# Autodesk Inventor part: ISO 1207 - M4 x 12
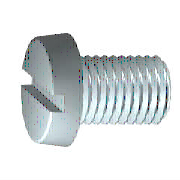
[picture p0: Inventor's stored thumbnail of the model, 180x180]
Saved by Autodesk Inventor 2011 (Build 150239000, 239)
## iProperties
IsCustomPart: 0
Created: 2010-02
Part Number: ISO 1207 - M4 x 12
Material: EdelStahl - 440C
Description: Zylinderkopfschrauben mit Schlitz - Produktklasse A
Document SubType Name: Modeling
Standard: ISO 1207
Designer: M.Schulte
Standard Revision: Third edition 1992-05-15
Standards Organization: ISO
Language: de-DE
Size Designation: M4 x 12
Categories: <MemberInstance><Categories><Category DisplayName="Verbindungselemente" InternalName="e4da775c-781d-43d5-af7c-5136215cf5a6" Mnemonic="FSTN"><Category DisplayNam
Density: 7.75 g/cm^3
Author: M.Schulte
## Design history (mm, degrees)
body "Solid1"
sketch "Sketch1"
  geometry: L1 (-2.6, 0)-(12, 0); L2 (12, 0)-(12, 2); L3 (12, 2)-(1.4, 2); L4 (1.4, 2)-(0.97, 1.785); L5 (0.97, 1.785)-(0, 1.785); L6 (0, 1.785)-(0, 3.5); L7 (-5.52, 0)-(14.92, 0) reference; L8 (0, -0.7)-(0, 4.2) reference; L9 (-2.6, 0)-(-2.6, 3.273); L10 (0, 3.5)-(-2.6, 3.273); L11 (1.4, 2)-(0, 2)
  constraints: 18 end point, 4 parallel, 2 collinear, 2 perpendicular, 1 horizontal, 1 point on line
  dimensions: "d0" = 12 distance between parallel lines of L2 L6 (= NLG); "d1" = 10.6 distance from line of L3.end L2 (= GEL); "d2" = 0.42952 horizontal distance of L4.end L3.end (computed from GAL); "d3" = 2.6 distance from line of L1.start L6 (= KOH); "d4" = 4 diameter of L3 L1 (= GD); "d5" = 3.5705 diameter of L5 L1 (= BDM); "d9" = 7 diameter of L6.end L1 (= KOD); "d10" = 5 deg angle of L10 L1 (= KEWI)
chamfer "Chamfer1" distance "d17" = 0.42941 (= -0.5 x SPD + 0.5 x GD); stored, may be unused: second distance "d18" = 0.42952 (computed from GUL), angle "d36" = 45 deg
sketch "Sketch2"
  geometry: L1 (0, 0)-(0, 3.273) reference; L2 (-3.5, 0.6)-(3.5, 0.6); L3 (3.5, 0.6)-(3.5, -0.6); L4 (3.5, -0.6)-(-3.5, -0.6); L5 (-3.5, -0.6)-(-3.5, 0.6); L6 (-3.5, 0)-(3.5, 0); L7 (0, 0.6)-(0, -0.6); C1 r 3.5 at (0, 0) reference; 1 further point
  constraints: 12 end point, 5 midpoint, 2 parallel, 1 collinear, 1 horizontal, 1 perpendicular
  dimensions: "d11" = 1.2 distance of L4.end L2.start (= SBR); "d12" = 7 distance of L2.start L2.end (= KOD)
extrude "Slot" cut sketch "Sketch2" distance "d19" = 1.1 (= STI); taper "d20" = 0 deg
workplane "Work Plane1"
revolve "Body" stored, may be unused: angle "d8" = 90 deg
fillet "Fillet1" dims "d14" = 0.2 (= RR)
feature "Thread" dims "d15" = 10.6 (= GEL), "d16" = 0
other parameters: "GD" = 4 (= NND) [user parameter; used in 2 equation terms], "NLG" = 12 [user parameter; used in 1 equation term], "GEL" = 10.6 [user parameter; used in 2 equation terms], "KOD" = 7 [user parameter; used in 2 equation terms], "KOH" = 2.6 [user parameter; used in 1 equation term], "GAL" = 0.42941 (= 0.61345 x PTC) [user parameter; used in 1 equation term], "SPD" = 3.14117 (= NND - 1.2269 x PTC) [user parameter; used in 1 equation term], "BDM" = 3.5705 [user parameter; used in 1 equation term], "GUL" = 0.42941 (= 0.61345 x PTC) [user parameter; used in 1 equation term], "RR" = 0.2 [user parameter; used in 1 equation term], "d7" = 0, "SBR" = 1.2 [user parameter; used in 1 equation term], "STI" = 1.1 [user parameter; used in 1 equation term], "KEWI" = 5 deg [user parameter; used in 1 equation term], "d37" = 0, "d39" = 0, "PTC" = 0.7 [user parameter; used in 5 equation terms], "THREADDIA" = 4 [user parameter; used in 1 equation term], "TOA" = 30 deg [user parameter], "TPU" = 14.28571 (computed from PTC) [user parameter], "NND" = 4 [user parameter; used in 2 equation terms], "GD1" = 3.14117 (= THREADDIA - 1.2269 x PTC) [user parameter]
